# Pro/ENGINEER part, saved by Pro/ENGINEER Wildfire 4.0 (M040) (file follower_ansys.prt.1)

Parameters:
  METRIC = "NO"

Other parameters: PITCH, DRILL_DIAMETER, THREAD_DIAMETER, THREADS_PER_INCH, THREAD_DEPTH, THREAD_LENGTH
